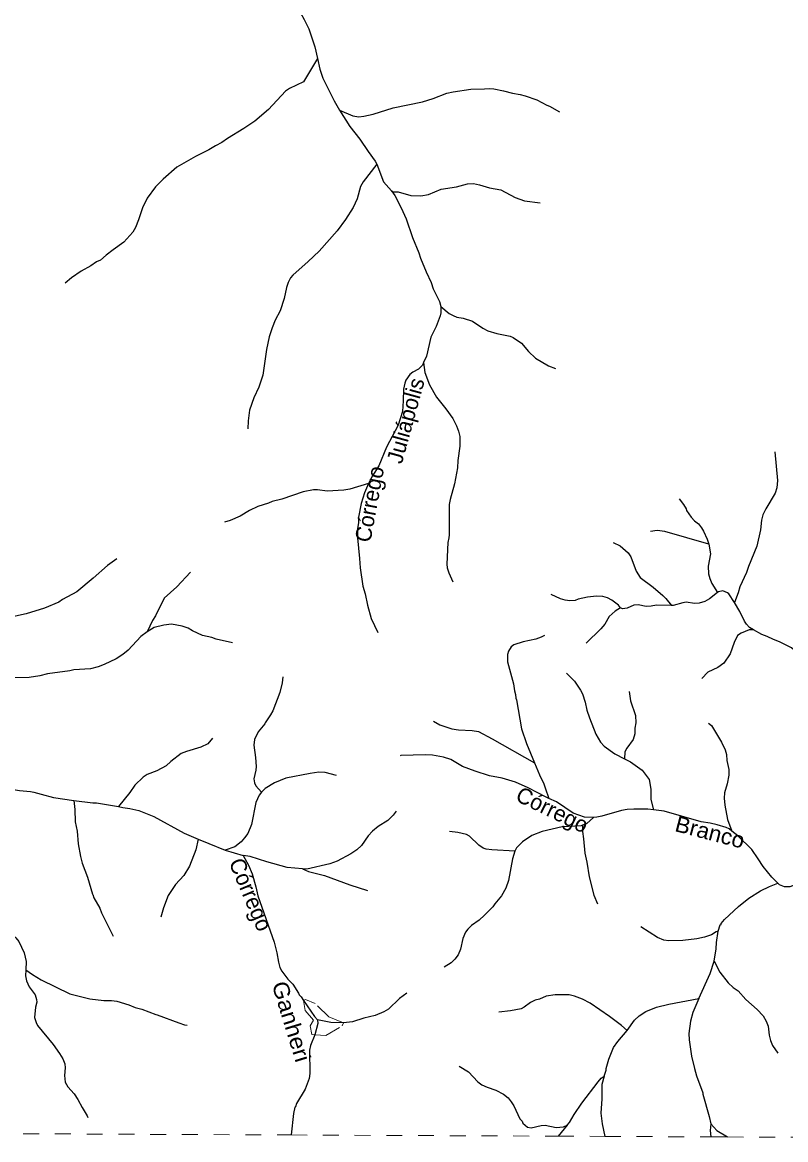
# Model space of a CAD drawing. Extents: x 551.6 to 577.6, y 7567 to 7594.7.
# Drawn here: x 569.17 to 573.98, y 7566.95 to 7573.99 of the extents above; entities that cross this region are included whole.
import ezdxf
from ezdxf.enums import TextEntityAlignment as Align

# ---------------------------------------------------------------- set-up
doc = ezdxf.new("R2010")
doc.units = 0
doc.header["$LTSCALE"] = 0.04
doc.linetypes.add('SHORT_DASHED', pattern=[2.7, 1.5, -1.2])
for name, color, linetype, lineweight in [('21', 7, 'SHORT_DASHED', 13), ('53', 7, 'SHORT_DASHED', 13), ('7', 7, 'Continuous', 25)]:
    doc.layers.add(name, color=color, linetype=linetype, lineweight=lineweight)
doc.layers.add('61', color=7, linetype='Continuous')

msp = doc.modelspace()

# ---------------------------------------------------------------- linework, layer by layer
at = {"layer": '21'}
for points in [[(571.1894, 7567.6887), (571.0976, 7567.7267), (571.0099, 7567.8096), (570.9501, 7567.8346), (570.9379, 7567.8288)], [(570.9379, 7567.8288), (570.9482, 7567.7658), (571.0001, 7567.7045), (570.9784, 7567.6687), (570.9898, 7567.6149), (571.0094, 7567.6124), (571.0099, 7567.6123)], [(571.0099, 7567.6123), (571.0773, 7567.6083), (571.181, 7567.6687), (571.1894, 7567.6887)]]:
    msp.add_lwpolyline(points, dxfattribs=at)
at = {"layer": '53'}
msp.add_lwpolyline([(551.613, 7567.0572), (552.9162, 7567.0524), (553.7221, 7567.0495), (554.9107, 7567.0451), (556.1477, 7567.0406), (557.2075, 7567.0367), (559.4055, 7567.0287), (559.6981, 7567.0276), (560.556, 7567.0244), (562.9715, 7567.0156), (564.6334, 7567.0092), (566.4358, 7567.0011), (566.7714, 7566.9996), (570.8595, 7566.9812), (572.5416, 7566.9737), (572.8363, 7566.9724), (573.5039, 7566.9694), (573.609, 7566.9689), (574.6855, 7566.9641), (575.0536, 7566.9624), (576.5544, 7566.9557), (577.1266, 7566.9531), (577.4204, 7566.9518)], dxfattribs=at)
at = {"layer": '7'}
msp.add_line((572.5979, 7567.0427), (572.5416, 7566.9737), dxfattribs=at)
for points in [[(570.6823, 7574.5674), (570.7145, 7574.4998), (570.8031, 7574.3501), (570.8192, 7574.3082), (570.8288, 7574.2503), (570.8505, 7574.1859), (570.8715, 7574.1408), (570.9423, 7574.0121), (570.9713, 7573.9525), (571.0083, 7573.8398), (571.0248, 7573.766)], [(571.0248, 7573.766), (570.9383, 7573.6201), (570.849, 7573.5774), (570.8248, 7573.5605), (570.7169, 7573.4447), (570.6309, 7573.3714), (570.5624, 7573.3255), (570.4586, 7573.2628), (570.4224, 7573.237), (570.383, 7573.2161)], [(571.0248, 7573.766), (571.0397, 7573.6998), (571.059, 7573.6418), (571.1306, 7573.5002), (571.1641, 7573.4399)], [(571.1641, 7573.4399), (571.2489, 7573.4052), (571.286, 7573.3996), (571.3182, 7573.402), (571.3761, 7573.4149), (571.5017, 7573.4551), (571.6868, 7573.4937), (571.7544, 7573.5147), (571.8397, 7573.5469), (571.8799, 7573.5565), (571.991, 7573.5734), (572.0779, 7573.575)], [(572.0779, 7573.575), (572.1117, 7573.5766), (572.1358, 7573.5742), (572.197, 7573.563), (572.2549, 7573.5469), (572.3032, 7573.5404), (572.3338, 7573.5316), (572.4079, 7573.505), (572.4706, 7573.4712), (572.4875, 7573.4656), (572.5503, 7573.4302)], [(571.1641, 7573.4399), (571.2288, 7573.3384), (571.2932, 7573.2572), (571.3447, 7573.1799), (571.3898, 7573.1203), (571.3989, 7573.1013)], [(570.383, 7573.2161), (570.3411, 7573.1903), (570.2558, 7573.1485), (570.1391, 7573.0809), (570.053, 7573.0068), (570.0055, 7572.9569), (569.9532, 7572.8853), (569.9226, 7572.8258), (569.8985, 7572.7485), (569.8783, 7572.7002), (569.8623, 7572.6713), (569.8043, 7572.6093), (569.7383, 7572.5594)], [(571.3989, 7573.1013), (571.3125, 7572.99), (571.2972, 7572.9594), (571.2763, 7572.8821), (571.2505, 7572.8274), (571.2014, 7572.7525), (571.1491, 7572.6809), (571.0365, 7572.5521), (570.9673, 7572.4861), (570.8707, 7572.4016), (570.8562, 7572.3831), (570.8417, 7572.3542), (570.8304, 7572.322), (570.8159, 7572.2544), (570.7902, 7572.1755), (570.7588, 7572.1176), (570.7403, 7572.0693)], [(571.3989, 7573.1013), (571.4405, 7572.99), (571.492, 7572.932)], [(571.492, 7572.932), (571.5032, 7572.9263), (571.5338, 7572.9256), (571.6143, 7572.903), (571.6771, 7572.8998), (571.7254, 7572.9095), (571.8059, 7572.9425), (571.9024, 7572.9585), (571.97, 7572.9763), (572.0087, 7572.9787), (572.0473, 7572.9706), (572.1101, 7572.9513), (572.1809, 7572.9384), (572.2702, 7572.8909), (572.329, 7572.8692), (572.4296, 7572.8564)], [(571.492, 7572.932), (571.5129, 7572.903), (571.5531, 7572.8258), (571.5837, 7572.755), (571.6232, 7572.6391), (571.6642, 7572.5425), (571.6755, 7572.5087)], [(569.7383, 7572.5594), (569.6933, 7572.5264), (569.6587, 7572.495), (569.6329, 7572.4837), (569.5975, 7572.4604), (569.5363, 7572.4266), (569.4752, 7572.3839), (569.4349, 7572.3501)], [(571.6755, 7572.5087), (571.7093, 7572.4218), (571.7415, 7572.3542), (571.7543, 7572.3155), (571.7954, 7572.2351), (571.8034, 7572.2038)], [(571.8034, 7572.2038), (571.8034, 7572.1642), (571.7994, 7572.1449), (571.7737, 7572.0773), (571.7407, 7572.0097), (571.7125, 7571.8906), (571.6944, 7571.8499)], [(571.8034, 7572.2038), (571.8558, 7572.1586), (571.8799, 7572.1457), (571.9041, 7572.136), (571.9427, 7572.1288), (572.0014, 7572.1111), (572.0666, 7572.0668), (572.0988, 7572.0499), (572.1551, 7572.0322), (572.2388, 7572.0169), (572.2582, 7572.0081), (572.3121, 7571.9719), (572.3555, 7571.9204), (572.3998, 7571.8785), (572.4803, 7571.8294), (572.5262, 7571.8117)], [(570.7403, 7572.0693), (570.721, 7572.0129), (570.7033, 7571.9325), (570.6807, 7571.7699), (570.6558, 7571.6958), (570.6236, 7571.6282), (570.597, 7571.5494), (570.589, 7571.4818), (570.5874, 7571.4327)], [(571.6944, 7571.8499), (571.6875, 7571.8343), (571.661, 7571.8077), (571.6256, 7571.7892), (571.6079, 7571.7755), (571.5813, 7571.7393), (571.5749, 7571.72), (571.5684, 7571.6814), (571.566, 7571.6089)], [(571.6944, 7571.8499), (571.7028, 7571.7876), (571.731, 7571.7087), (571.7745, 7571.6315), (571.8348, 7571.5574), (571.8783, 7571.4963), (571.9024, 7571.4512), (571.9145, 7571.4174), (571.9217, 7571.3836), (571.9233, 7571.3224), (571.9105, 7571.2323), (571.9081, 7571.1872), (571.8879, 7571.0858), (571.8606, 7570.9876), (571.8549, 7570.9554), (571.8549, 7570.7639)], [(571.566, 7571.6089), (571.5604, 7571.5413), (571.5346, 7571.4544), (571.4598, 7571.316), (571.4123, 7571.1993), (571.3721, 7571.1357), (571.3471, 7571.0871)], [(573.908, 7571.2878), (573.9241, 7571.1067), (573.9193, 7571.0601), (573.9096, 7571.0262), (573.8517, 7570.9288), (573.8323, 7570.8894), (573.8235, 7570.8556), (573.8178, 7570.7961), (573.7937, 7570.6931), (573.7406, 7570.5643), (573.7285, 7570.5273), (573.6859, 7570.4371), (573.6762, 7570.3985), (573.6542, 7570.3384)], [(571.3471, 7571.0871), (571.2296, 7571.052), (571.191, 7571.0447), (571.0864, 7571.0391), (571.0252, 7571.0472), (571.0011, 7571.0472), (570.9351, 7571.0359), (570.7999, 7570.9892), (570.7403, 7570.9731), (570.7162, 7570.9626), (570.6494, 7570.9425), (570.597, 7570.9176), (570.5391, 7570.8814), (570.4747, 7570.854), (570.4401, 7570.8436)], [(571.3471, 7571.0871), (571.3222, 7571.0295), (571.3012, 7570.9619), (571.2835, 7570.8749), (571.2835, 7570.8428), (571.2779, 7570.8025), (571.2779, 7570.7446), (571.2892, 7570.6142)], [(573.3036, 7570.9916), (573.3317, 7570.9554), (573.3478, 7570.9289), (573.3511, 7570.9176), (573.38, 7570.8749), (573.4002, 7570.8516), (573.4259, 7570.8323), (573.4452, 7570.8089), (573.4589, 7570.7864), (573.4814, 7570.7365), (573.4911, 7570.7053)], [(573.4911, 7570.7053), (573.2143, 7570.784), (573.166, 7570.792), (573.1233, 7570.7856)], [(571.8549, 7570.7639), (571.8541, 7570.7446), (571.8477, 7570.7156), (571.8413, 7570.5788), (571.8437, 7570.5562), (571.8533, 7570.5241), (571.8775, 7570.4685)], [(572.8883, 7570.7148), (572.9318, 7570.6939), (572.9841, 7570.6496), (573.0002, 7570.6255), (573.0332, 7570.5353), (573.0597, 7570.4943), (573.1418, 7570.4339), (573.2014, 7570.3816), (573.2207, 7570.3631), (573.2569, 7570.3183)], [(573.4911, 7570.7053), (573.5024, 7570.6448), (573.4871, 7570.5659), (573.4887, 7570.5176), (573.4975, 7570.4886), (573.5112, 7570.4581), (573.5459, 7570.4006)], [(569.7609, 7570.6118), (569.7021, 7570.5715), (569.6112, 7570.4902), (569.509, 7570.4057), (569.4188, 7570.3574), (569.3947, 7570.3389), (569.3045, 7570.3019), (569.1887, 7570.2657), (569.0856, 7570.244), (569.0599, 7570.2343), (568.9698, 7570.19), (568.9054, 7570.1498), (568.7959, 7570.0621), (568.7581, 7570.0355), (568.6945, 7569.976), (568.6659, 7569.9382)], [(571.2892, 7570.6142), (571.294, 7570.5562), (571.3117, 7570.4404), (571.3254, 7570.3921), (571.3399, 7570.3212), (571.3632, 7570.2359), (571.4051, 7570.1482)], [(570.2244, 7570.5281), (570.1383, 7570.4363), (570.0594, 7570.3647), (570.0039, 7570.2536), (569.9854, 7570.2247), (569.9525, 7570.1536)], [(572.9342, 7570.3031), (572.9221, 7570.3204), (572.8803, 7570.3526), (572.8521, 7570.3679), (572.8231, 7570.376), (572.7845, 7570.3776), (572.7266, 7570.3711), (572.6686, 7570.3582), (572.6493, 7570.351), (572.6155, 7570.3478), (572.5865, 7570.3518), (572.5575, 7570.3599), (572.4988, 7570.388)], [(573.5459, 7570.4006), (573.4959, 7570.3599), (573.4654, 7570.3438), (573.4316, 7570.3325), (573.401, 7570.3309), (573.3495, 7570.3389)], [(573.6542, 7570.3384), (573.6183, 7570.3912), (573.6086, 7570.3985), (573.5796, 7570.4114), (573.5522, 7570.4057), (573.5459, 7570.4006)], [(572.9342, 7570.3031), (572.9004, 7570.2826), (572.8625, 7570.2488), (572.8352, 7570.2005), (572.8102, 7570.1707), (572.7185, 7570.0822)], [(573.2569, 7570.3183), (573.1611, 7570.3212), (573.1273, 7570.314), (573.0968, 7570.3132), (573.0461, 7570.3228), (573.0195, 7570.3212), (572.976, 7570.3019), (572.9469, 7570.2979), (572.9342, 7570.3031)], [(573.3495, 7570.3389), (573.3269, 7570.3357), (573.2658, 7570.318), (573.2569, 7570.3183)], [(573.7723, 7570.166), (573.747, 7570.1804), (573.7285, 7570.2005), (573.7164, 7570.2198), (573.6875, 7570.2818), (573.6542, 7570.3384)], [(569.9525, 7570.1536), (569.9114, 7570.124), (569.8333, 7570.0371), (569.7987, 7570.009), (569.7576, 7569.9824), (569.6812, 7569.9462)], [(570.49, 7570.083), (570.3878, 7570.1055), (570.3588, 7570.116), (570.3009, 7570.1297), (570.2381, 7570.1587), (570.2108, 7570.1748), (570.1737, 7570.1884), (570.1061, 7570.2005), (570.0578, 7570.1949), (569.9967, 7570.1796), (569.9525, 7570.1536)], [(573.7723, 7570.166), (573.7454, 7570.1651), (573.6963, 7570.1442), (573.673, 7570.1289), (573.6521, 7570.0846), (573.6255, 7570.0138), (573.5853, 7569.955), (573.5475, 7569.9269), (573.4863, 7569.8979), (573.4468, 7569.8585)], [(574.0817, 7569.9908), (574.0126, 7570.0508), (573.937, 7570.0902), (573.8983, 7570.1039), (573.8597, 7570.124), (573.8259, 7570.1353), (573.7723, 7570.166)], [(572.4569, 7570.1297), (572.4352, 7570.1184), (572.4014, 7570.1071), (572.3225, 7570.0903), (572.2638, 7570.0709), (572.2452, 7570.0581), (572.2292, 7570.0315), (572.2227, 7570.009), (572.2227, 7569.9639), (572.2598, 7569.8255), (572.267, 7569.7804), (572.2742, 7569.7579), (572.2758, 7569.7354), (572.2799, 7569.7241), (572.3113, 7569.5406), (572.3426, 7569.4488), (572.3926, 7569.327)], [(569.6812, 7569.9462), (569.6442, 7569.9317), (569.5959, 7569.9196), (569.4897, 7569.914), (569.4655, 7569.9059), (569.3239, 7569.8882), (569.2756, 7569.8746), (569.2096, 7569.8641), (569.0325, 7569.8617), (568.9231, 7569.8673), (568.8748, 7569.8657), (568.7702, 7569.8721)], [(570.8063, 7569.8681), (570.8039, 7569.8319), (570.7886, 7569.7708), (570.7435, 7569.6549), (570.7298, 7569.6291), (570.6952, 7569.58), (570.6936, 7569.5735), (570.651, 7569.5229), (570.6284, 7569.4746), (570.6244, 7569.4376), (570.6357, 7569.3603), (570.6389, 7569.304), (570.6373, 7569.2814), (570.6244, 7569.2251), (570.6284, 7569.201), (570.6373, 7569.1824), (570.6729, 7569.1417)], [(572.5954, 7569.8915), (572.6444, 7569.8416), (572.6831, 7569.7852), (572.696, 7569.7611), (572.7129, 7569.7096), (572.7233, 7569.6581), (572.7394, 7569.6098), (572.7805, 7569.5084), (572.8094, 7569.4569), (572.832, 7569.4327), (572.8988, 7569.3828), (572.9601, 7569.3516)], [(572.9889, 7569.7764), (572.9986, 7569.7176), (573.0291, 7569.6243), (573.0324, 7569.5792), (573.0259, 7569.5454), (573.0243, 7569.51), (573.0147, 7569.4746), (572.9744, 7569.4199), (572.9615, 7569.3957), (572.9601, 7569.3516)], [(571.7568, 7569.5889), (571.7962, 7569.5671), (571.8719, 7569.5414), (571.9137, 7569.5349), (572.0006, 7569.5309), (572.0393, 7569.5237), (572.1262, 7569.4786), (572.3926, 7569.327)], [(573.4903, 7569.576), (573.5088, 7569.5631), (573.5716, 7569.4569), (573.5941, 7569.4086), (573.6038, 7569.3788), (573.6046, 7569.341), (573.6183, 7569.2847), (573.6183, 7569.2493), (573.607, 7569.1945), (573.5909, 7569.1382), (573.5877, 7569.1044), (573.5925, 7569.0593), (573.6094, 7568.9692), (573.6375, 7568.8959)], [(570.3637, 7569.4818), (570.3339, 7569.4472), (570.2896, 7569.4255), (570.1995, 7569.3989), (570.1673, 7569.3852), (570.1021, 7569.3354), (570.0723, 7569.3088), (570.0128, 7569.2774), (569.9532, 7569.2533), (569.9275, 7569.2372), (569.8743, 7569.1856), (569.8429, 7569.1406), (569.7706, 7569.0512)], [(572.4658, 7569.1108), (572.3531, 7569.1696), (572.2743, 7569.205), (572.189, 7569.2299), (572.1101, 7569.2444), (572.0183, 7569.2742), (571.9395, 7569.3048), (571.8662, 7569.3482), (571.8204, 7569.3619), (571.7511, 7569.3756), (571.7061, 7569.3772), (571.5515, 7569.3724), (571.5459, 7569.3716)], [(568.2326, 7569.3249), (568.3018, 7569.2943), (568.342, 7569.2863), (568.3806, 7569.2855), (568.4193, 7569.2806), (568.4531, 7569.2726), (568.5995, 7569.2122), (568.6977, 7569.1832), (568.7653, 7569.1688), (568.8329, 7569.1599), (568.9134, 7569.1559), (569.0856, 7569.1623), (569.1484, 7569.1527), (569.216, 7569.147), (569.2386, 7569.143), (569.2836, 7569.1285)], [(572.3926, 7569.327), (572.4239, 7569.2509), (572.4521, 7569.1945), (572.4601, 7569.1688), (572.4837, 7569.1027)], [(572.9601, 7569.3516), (572.997, 7569.3329), (573.071, 7569.2798), (573.1161, 7569.2219), (573.1257, 7569.1607), (573.1257, 7569.0963), (573.1432, 7569.0307)], [(571.1451, 7569.2476), (571.0735, 7569.2661), (571.0333, 7569.2677), (570.9801, 7569.2605), (570.8256, 7569.2299), (570.7548, 7569.2001), (570.6952, 7569.1655), (570.6729, 7569.1417)], [(569.2836, 7569.1285), (569.3625, 7569.1076), (569.4898, 7569.0905)], [(569.4898, 7569.0905), (569.4961, 7569.0336), (569.4993, 7568.9547), (569.5106, 7568.8967), (569.517, 7568.8163), (569.5315, 7568.7374), (569.5435, 7568.6939), (569.5757, 7568.6054), (569.6071, 7568.4984), (569.6104, 7568.4968), (569.6168, 7568.4766), (569.6538, 7568.4107), (569.6635, 7568.3817), (569.7375, 7568.2344)], [(569.4898, 7569.0905), (569.6104, 7569.0738), (569.6329, 7569.0738), (569.7706, 7569.0512)], [(570.6729, 7569.1417), (570.6582, 7569.1229), (570.6373, 7569.077), (570.6091, 7568.9386), (570.5858, 7568.8807), (570.5665, 7568.8533), (570.5439, 7568.8283), (570.5053, 7568.7985), (570.4427, 7568.7766)], [(572.7639, 7568.9827), (572.7072, 7568.9853), (572.6372, 7569.0094), (572.5318, 7569.081), (572.4837, 7569.1027), (572.4658, 7569.1108)], [(569.7706, 7569.0512), (569.7987, 7569.0448), (569.8438, 7569.04), (569.9001, 7569.0255), (569.9935, 7568.9885), (570.185, 7568.8839), (570.2744, 7568.8448), (570.3411, 7568.8187), (570.4427, 7568.7766), (570.5572, 7568.743)], [(571.5218, 7569.0215), (571.5033, 7568.9965), (571.4679, 7568.9635), (571.4075, 7568.9265), (571.3729, 7568.8959), (571.3439, 7568.867), (571.302, 7568.8058), (571.2731, 7568.7792), (571.2361, 7568.7535), (571.1499, 7568.7068), (571.1025, 7568.6899), (570.9576, 7568.6561), (570.9309, 7568.6587)], [(573.1432, 7569.0307), (573.108, 7569.0352), (573.0179, 7569.0352), (572.976, 7569.0319), (572.9422, 7569.0271), (572.8183, 7568.9901), (572.7861, 7568.9836), (572.7639, 7568.9827)], [(573.5442, 7568.9354), (573.4992, 7568.9466), (573.4428, 7568.9547), (573.2094, 7569.0223), (573.1432, 7569.0307)], [(572.7639, 7568.9827), (572.7233, 7568.945), (572.6946, 7568.9338)], [(572.2701, 7568.7699), (572.1246, 7568.7776), (572.0892, 7568.7824), (572.0698, 7568.7897), (572.0417, 7568.8082), (571.9837, 7568.8637), (571.9644, 7568.875), (571.9105, 7568.8887), (571.8582, 7568.8951)], [(572.6946, 7568.9338), (572.6863, 7568.9305), (572.5672, 7568.9225), (572.4417, 7568.8951), (572.3757, 7568.8694), (572.3169, 7568.8283), (572.2799, 7568.7905), (572.2701, 7568.7699)], [(572.6946, 7568.9338), (572.6951, 7568.8935), (572.7024, 7568.8469), (572.7096, 7568.7567), (572.7225, 7568.7004), (572.7378, 7568.6094), (572.766, 7568.4927), (572.7909, 7568.4372)], [(573.6375, 7568.8959), (573.6199, 7568.9104), (573.6006, 7568.9193), (573.5442, 7568.9354)], [(573.9257, 7568.5682), (573.8879, 7568.6054), (573.8339, 7568.6738), (573.8034, 7568.7221), (573.7615, 7568.78), (573.6738, 7568.8661), (573.6375, 7568.8959)], [(570.2744, 7568.8448), (570.259, 7568.7776), (570.2188, 7568.6762), (570.1834, 7568.6167), (570.1311, 7568.5595), (570.0852, 7568.4911), (570.0546, 7568.4123), (570.0377, 7568.3535)], [(570.7065, 7568.7028), (570.6003, 7568.7374), (570.5572, 7568.743)], [(570.5572, 7568.743), (570.5898, 7568.6827), (570.6131, 7568.6263), (570.6373, 7568.5459), (570.6502, 7568.4895), (570.7532, 7568.1966), (570.7693, 7568.129), (570.7789, 7568.071), (570.7886, 7568.0372), (570.7998, 7568.0147), (570.8192, 7567.9881), (570.8385, 7567.9632), (570.8707, 7567.931), (570.9061, 7567.8747), (570.9093, 7567.865), (570.9227, 7567.8514), (570.9379, 7567.8288)], [(572.2701, 7568.7699), (572.2549, 7568.7213), (572.2292, 7568.5861), (572.2115, 7568.5378), (572.1857, 7568.4895), (572.1439, 7568.438)], [(574.5164, 7568.7905), (574.4569, 7568.7623), (574.4279, 7568.7438), (574.3329, 7568.6947), (574.1913, 7568.6352), (574.0352, 7568.5571), (574.0014, 7568.5458), (573.9676, 7568.5458), (573.937, 7568.5571), (573.9257, 7568.5682)], [(570.9309, 7568.6587), (570.8353, 7568.6682), (570.7065, 7568.7028)], [(570.9309, 7568.6587), (570.9689, 7568.6424), (571.0703, 7568.6167), (571.2296, 7568.5579), (571.3399, 7568.5217)], [(573.5509, 7568.2654), (573.564, 7568.3054), (573.5684, 7568.3076), (573.57, 7568.3141), (573.5901, 7568.339), (573.6778, 7568.4219), (573.7438, 7568.4734), (573.8166, 7568.521), (573.8742, 7568.5483), (573.9257, 7568.5682)], [(568.8635, 7568.3833), (568.944, 7568.3623), (569.0084, 7568.3277), (569.055, 7568.2899), (569.1243, 7568.2247), (569.1436, 7568.2014), (569.1774, 7568.129), (569.1902, 7568.0742), (569.1885, 7568.0219)], [(572.1439, 7568.438), (572.1294, 7568.4187), (572.0779, 7568.3672), (572.0433, 7568.3358), (571.9958, 7568.3012), (571.9724, 7568.2787), (571.9588, 7568.2593), (571.9411, 7568.2207), (571.9258, 7568.1531), (571.9113, 7568.1161), (571.8912, 7568.0903), (571.867, 7568.0662), (571.8244, 7568.0396)], [(573.5509, 7568.2654), (573.537, 7568.2609), (573.5088, 7568.2432), (573.4638, 7568.2287), (573.4155, 7568.2175), (573.3269, 7568.2078), (573.24, 7568.2054), (573.2078, 7568.2094), (573.1676, 7568.2255), (573.0622, 7568.2939)], [(573.5246, 7568.0766), (573.5378, 7568.1547), (573.5394, 7568.195), (573.5509, 7568.2654)], [(572.9776, 7567.6399), (573.0235, 7567.7048), (573.0533, 7567.7314), (573.0943, 7567.7587), (573.1611, 7567.7861), (573.24, 7567.8054), (573.428, 7567.8419), (573.5008, 7567.9986), (573.5246, 7568.0766)], [(573.5246, 7568.0766), (573.5619, 7568.0066), (573.6134, 7567.9406), (573.6456, 7567.9117), (573.677, 7567.8899), (573.7245, 7567.8352), (573.7953, 7567.7732), (573.8331, 7567.733), (573.8533, 7567.6992), (573.8645, 7567.667), (573.871, 7567.6107), (573.8798, 7567.5769), (573.8919, 7567.5463), (573.9257, 7567.4972)], [(569.1885, 7568.0219), (569.1854, 7567.9841), (569.1927, 7567.9519), (569.2096, 7567.9157), (569.2458, 7567.865), (569.2554, 7567.836), (569.2579, 7567.8183), (569.2482, 7567.7861), (569.2426, 7567.7217), (569.2522, 7567.6895), (569.2619, 7567.671)], [(569.1885, 7568.0219), (569.2305, 7567.9921), (569.2852, 7567.9591), (569.4655, 7567.8714), (569.5911, 7567.8384), (569.6796, 7567.8296), (569.7279, 7567.8296), (569.7601, 7567.8239), (569.8373, 7567.8022), (569.8776, 7567.7845), (569.9178, 7567.774), (570.0063, 7567.7402)], [(570.9379, 7567.8288), (571.0059, 7567.7273), (571.0256, 7567.7076)], [(571.5878, 7567.8755), (571.5427, 7567.8408), (571.4727, 7567.7748), (571.4437, 7567.7579), (571.389, 7567.7346), (571.3182, 7567.7169), (571.2457, 7567.6944), (571.1894, 7567.6887)], [(572.9776, 7567.6399), (572.9406, 7567.6718), (572.865, 7567.7282), (572.7443, 7567.8111), (572.696, 7567.8376), (572.6445, 7567.8569), (572.6107, 7567.865), (572.5237, 7567.865), (572.4658, 7567.8569), (572.424, 7567.8376), (572.3966, 7567.832), (572.3684, 7567.8167), (572.3282, 7567.7861), (572.3097, 7567.7764), (572.2421, 7567.7628), (572.1688, 7567.7555)], [(573.428, 7567.8419), (573.3897, 7567.7539), (573.3752, 7567.6976), (573.3655, 7567.6203), (573.3672, 7567.5801), (573.3816, 7567.4787), (573.401, 7567.3998), (573.4138, 7567.3548), (573.4541, 7567.2469), (573.4541, 7567.2389), (573.4943, 7567.0972), (573.5032, 7567.0505)], [(570.0063, 7567.7402), (570.0144, 7567.7394), (570.1512, 7567.6871), (570.1882, 7567.675), (570.2051, 7567.6735)], [(571.0256, 7567.7076), (571.0268, 7567.6831), (571.0094, 7567.6124)], [(571.1894, 7567.6887), (571.1105, 7567.6911), (571.0256, 7567.7076)], [(569.2619, 7567.671), (569.3593, 7567.5519), (569.4003, 7567.4948), (569.4204, 7567.461), (569.4325, 7567.4288), (569.4349, 7567.4047), (569.4317, 7567.3564), (569.4349, 7567.3145), (569.4526, 7567.2839), (569.4929, 7567.2405), (569.5162, 7567.2051), (569.5427, 7567.1536), (569.5749, 7567.102), (569.5782, 7567.0916)], [(571.0094, 7567.6124), (570.9825, 7567.5447), (570.9753, 7567.5157), (570.9769, 7567.3692), (570.9729, 7567.337), (570.9471, 7567.2694), (570.8932, 7567.1801), (570.8868, 7567.1584), (570.8835, 7567.1568), (570.8747, 7567.1165), (570.8595, 7566.9812)], [(572.8323, 7567.353), (572.8455, 7567.3903), (572.844, 7567.3998), (572.8609, 7567.4594), (572.8907, 7567.5318), (572.9173, 7567.5704), (572.9776, 7567.6399)], [(571.9177, 7567.4143), (571.9781, 7567.3797), (572.036, 7567.3169), (572.061, 7567.2976), (572.094, 7567.2823), (572.1503, 7567.263), (572.1978, 7567.238), (572.2268, 7567.2155), (572.2469, 7567.1906), (572.2622, 7567.1648), (572.3016, 7567.0827), (572.3145, 7567.0674), (572.3193, 7567.0562), (572.3483, 7567.0304), (572.3724, 7567.0264), (572.4352, 7567.0417), (572.461, 7567.0425), (572.5298, 7567.0286), (572.5527, 7567.0296), (572.5753, 7567.0328), (572.5979, 7567.0427)], [(572.6903, 7567.1817), (572.7941, 7567.3169), (572.8126, 7567.3386), (572.8323, 7567.353)], [(572.8323, 7567.353), (572.8183, 7567.3), (572.8183, 7567.2083), (572.8118, 7567.1181), (572.8199, 7567.0521), (572.8363, 7566.9724)], [(572.5979, 7567.0427), (572.6139, 7567.0602), (572.6428, 7567.1101), (572.6903, 7567.1817)], [(573.5032, 7567.0505), (573.5, 7567.0087), (573.5039, 7566.9694)], [(573.5032, 7567.0505), (573.5426, 7567.0095), (573.609, 7566.9689)]]:
    msp.add_lwpolyline(points, dxfattribs=at)

# ---------------------------------------------------------------- texts
at = {"layer": '61'}
for s, rotation, p in [('Juliápolis', 74.698, (571.6293, 7571.4711)), ('Córrego', 79.445, (571.4024, 7570.9487)), ('Córrego', 334.131, (572.4836, 7568.9863)), ('Córrego', 292.79, (570.5583, 7568.4776))]:
    msp.add_text(s, height=0.1, rotation=rotation, dxfattribs=at).set_placement(p, align=Align.CENTER)
for s, rotation, width, p in [('Branco', 345.429, 1.05, (573.4864, 7568.8418)), ('Ganheri', 287.059, 1.1, (570.813, 7567.6816))]:
    msp.add_text(s, height=0.1, rotation=rotation, dxfattribs=dict(at, width=width)).set_placement(p, align=Align.CENTER)

doc.saveas('drawing.dxf')
